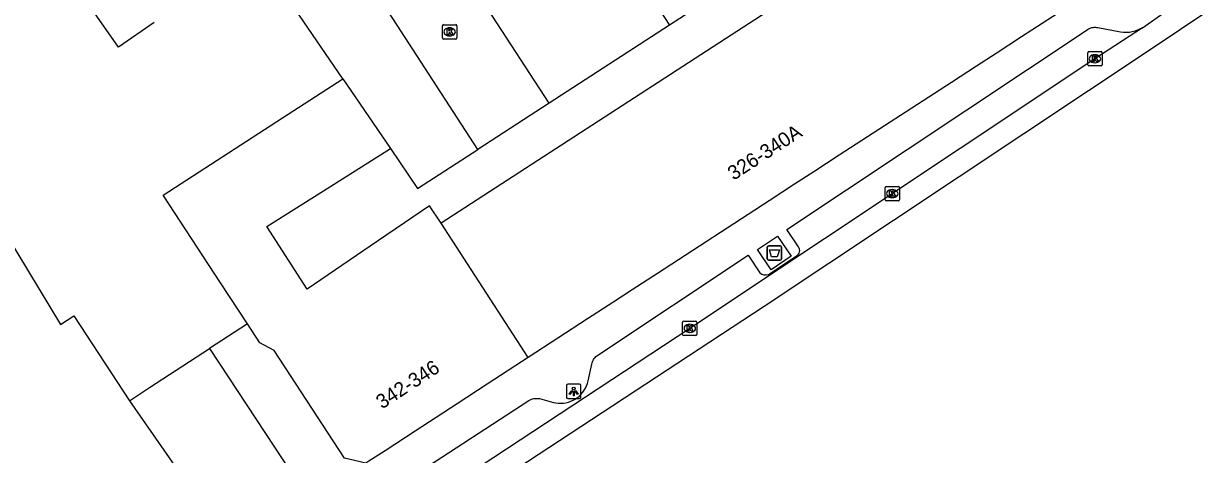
# Model space of a CAD drawing. Extents: x 159222 to 160346, y 381249 to 382166.
# Drawn here: x 160056.7 to 160138.9, y 381586.7 to 381616.7 of the extents above; entities that cross this region are included whole.
import ezdxf

# ---------------------------------------------------------------- set-up
doc = ezdxf.new("R2010")
doc.units = 0
for name, color, linetype in [('IMGEO_Afval_apart_plaats', 7, 'Continuous'), ('IMGEO_Kolk', 7, 'Continuous'), ('IMGEO_Lichtpunt', 7, 'Continuous'), ('IMGEO_Pand', 7, 'Continuous'), ('IMGEO_Pand_nummerreeks', 7, 'Continuous'), ('IMGEO_Pand_overbouw', 7, 'Continuous'), ('IMGEO_Parkeervlak_open', 7, 'Continuous'), ('IMGEO_Rijbaan_lokaal_gesloten', 7, 'Continuous'), ('IMGEO_Rijbaan_lokaal_open', 7, 'Continuous'), ('IMGEO_Voetpad_gesloten', 7, 'Continuous'), ('IMGEO_Voetpad_open', 7, 'Continuous')]:
    doc.layers.add(name, color=color, linetype=linetype)

msp = doc.modelspace()

# ---------------------------------------------------------------- linework, layer by layer
at = {"layer": 'IMGEO_Afval_apart_plaats'}
for p, q in [((160108.477, 381600.312), (160108.477, 381601.112)), ((160108.477, 381601.112), (160108.477, 381600.312)), ((160108.577, 381601.212), (160109.367, 381601.212)), ((160109.367, 381601.212), (160108.577, 381601.212)), ((160109.467, 381601.112), (160109.467, 381600.312)), ((160109.467, 381600.312), (160109.467, 381601.112)), ((160109.367, 381600.212), (160108.577, 381600.212)), ((160108.577, 381600.212), (160109.367, 381600.212))]:
    msp.add_line(p, q, dxfattribs=at)
msp.add_lwpolyline([(160108.62, 381600.926), (160109.324, 381600.926), (160109.175, 381600.456), (160108.769, 381600.456), (160108.62, 381600.926)], dxfattribs=at)
for centre, start, end in [((160108.577, 381601.112), 90, 180), ((160108.577, 381601.112), 90, 180), ((160109.367, 381601.112), 0, 90), ((160109.367, 381601.112), 360, 90), ((160108.577, 381600.312), 180, 270), ((160108.577, 381600.312), 180, 270), ((160109.367, 381600.312), 270, 0), ((160109.367, 381600.312), 270, 0)]:
    msp.add_arc(centre, 0.1, start, end, dxfattribs=at)
at = {"layer": 'IMGEO_Kolk'}
for p, q in [((160085.845, 381615.716), (160085.845, 381616.568)), ((160085.92, 381616.642), (160086.772, 381616.642)), ((160086.333, 381616.422), (160086.358, 381616.422)), ((160086.846, 381616.568), (160086.846, 381615.716)), ((160086.772, 381615.642), (160085.92, 381615.642)), ((160086.356, 381615.862), (160086.331, 381615.862)), ((160130.8, 381613.837), (160130.8, 381614.689)), ((160130.875, 381614.763), (160131.727, 381614.763)), ((160131.801, 381614.689), (160131.801, 381613.837)), ((160131.727, 381613.763), (160130.875, 381613.763)), ((160131.311, 381613.983), (160131.286, 381613.983)), ((160131.288, 381614.543), (160131.313, 381614.543)), ((160116.68, 381604.43), (160116.68, 381605.282)), ((160116.755, 381605.356), (160117.607, 381605.356)), ((160117.168, 381605.136), (160117.193, 381605.136)), ((160117.681, 381605.282), (160117.681, 381604.43)), ((160117.607, 381604.356), (160116.755, 381604.356)), ((160117.191, 381604.576), (160117.166, 381604.576)), ((160102.576, 381595.035), (160102.576, 381595.887)), ((160102.651, 381595.961), (160103.503, 381595.961)), ((160103.064, 381595.741), (160103.089, 381595.741)), ((160103.577, 381595.887), (160103.577, 381595.035)), ((160103.503, 381594.961), (160102.651, 381594.961)), ((160103.087, 381595.181), (160103.062, 381595.181))]:
    msp.add_line(p, q, dxfattribs=at)
for points in [[(160085.845, 381615.716), (160085.845, 381616.568)], [(160085.92, 381616.642), (160086.772, 381616.642)], [(160086.166, 381616.342), (160086.289, 381616.342), (160086.289, 381616.191), (160086.419, 381616.342), (160086.583, 381616.342), (160086.437, 381616.191), (160086.59, 381615.942), (160086.438, 381615.942), (160086.353, 381616.106), (160086.289, 381616.039), (160086.289, 381615.942), (160086.166, 381615.942), (160086.166, 381616.342)], [(160086.846, 381616.568), (160086.846, 381615.716)], [(160086.772, 381615.642), (160085.92, 381615.642)], [(160130.8, 381613.837), (160130.8, 381614.689)], [(160130.875, 381614.763), (160131.727, 381614.763)], [(160131.801, 381614.689), (160131.801, 381613.837)], [(160131.727, 381613.763), (160130.875, 381613.763)], [(160131.121, 381614.463), (160131.244, 381614.463), (160131.244, 381614.312), (160131.374, 381614.463), (160131.538, 381614.463), (160131.392, 381614.312), (160131.545, 381614.063), (160131.393, 381614.063), (160131.308, 381614.227), (160131.244, 381614.16), (160131.244, 381614.063), (160131.121, 381614.063), (160131.121, 381614.463)], [(160116.68, 381604.43), (160116.68, 381605.282)], [(160116.755, 381605.356), (160117.607, 381605.356)], [(160117.001, 381605.056), (160117.124, 381605.056), (160117.124, 381604.905), (160117.254, 381605.056), (160117.418, 381605.056), (160117.272, 381604.905), (160117.425, 381604.656), (160117.273, 381604.656), (160117.188, 381604.82), (160117.124, 381604.753), (160117.124, 381604.656), (160117.001, 381604.656), (160117.001, 381605.056)], [(160117.681, 381605.282), (160117.681, 381604.43)], [(160117.607, 381604.356), (160116.755, 381604.356)], [(160102.576, 381595.035), (160102.576, 381595.887)], [(160102.651, 381595.961), (160103.503, 381595.961)], [(160102.897, 381595.661), (160103.02, 381595.661), (160103.02, 381595.51), (160103.15, 381595.661), (160103.314, 381595.661), (160103.168, 381595.51), (160103.321, 381595.261), (160103.169, 381595.261), (160103.084, 381595.425), (160103.02, 381595.358), (160103.02, 381595.261), (160102.897, 381595.261), (160102.897, 381595.661)], [(160103.577, 381595.887), (160103.577, 381595.035)], [(160103.503, 381594.961), (160102.651, 381594.961)]]:
    msp.add_lwpolyline(points, dxfattribs=at)
for centre, start, end in [((160085.922, 381616.566), 91.55205, 178.44795), ((160085.922, 381616.566), 91.55205, 178.44795), ((160086.77, 381616.566), 1.55205, 88.44795), ((160086.77, 381616.566), 1.55205, 88.44795), ((160085.922, 381615.718), 181.55205, 268.44795), ((160085.922, 381615.718), 181.55205, 268.44795), ((160086.77, 381615.718), 271.55205, 358.44795), ((160086.77, 381615.718), 271.55205, 358.44795), ((160130.877, 381614.687), 91.55205, 178.44795), ((160130.877, 381614.687), 91.55205, 178.44795), ((160131.725, 381614.687), 1.55205, 88.44795), ((160131.725, 381614.687), 1.55205, 88.44795), ((160130.877, 381613.839), 181.55205, 268.44795), ((160130.877, 381613.839), 181.55205, 268.44795), ((160131.725, 381613.839), 271.55205, 358.44795), ((160131.725, 381613.839), 271.55205, 358.44795), ((160116.757, 381605.28), 91.55205, 178.44795), ((160116.757, 381605.28), 91.55205, 178.44795), ((160117.605, 381605.28), 1.55205, 88.44795), ((160117.605, 381605.28), 1.55205, 88.44795), ((160116.757, 381604.432), 181.55205, 268.44795), ((160116.757, 381604.432), 181.55205, 268.44795), ((160117.605, 381604.432), 271.55205, 358.44795), ((160117.605, 381604.432), 271.55205, 358.44795), ((160102.653, 381595.885), 91.55205, 178.44795), ((160102.653, 381595.885), 91.55205, 178.44795), ((160103.501, 381595.885), 1.55205, 88.44795), ((160103.501, 381595.885), 1.55205, 88.44795), ((160102.653, 381595.037), 181.55205, 268.44795), ((160102.653, 381595.037), 181.55205, 268.44795), ((160103.501, 381595.037), 271.55205, 358.44795), ((160103.501, 381595.037), 271.55205, 358.44795)]:
    msp.add_arc(centre, 0.0765, start, end, dxfattribs=at)
for centre, major_axis, ratio, start_param, end_param in [((160086.332, 381616.142), (-0.387, 0.002), 0.722429, 4.712389, 7.853982), ((160086.357, 381616.142), (-0.39, 0.002), 0.717154, 1.570796, 4.712389), ((160131.287, 381614.263), (-0.387, 0.002), 0.722429, 4.712389, 7.853982), ((160131.312, 381614.263), (-0.39, 0.002), 0.717154, 1.570796, 4.712389), ((160117.167, 381604.856), (-0.387, 0.002), 0.722429, 4.712389, 7.853982), ((160117.192, 381604.856), (-0.39, 0.002), 0.717154, 1.570796, 4.712389), ((160103.063, 381595.461), (-0.387, 0.002), 0.722429, 4.712389, 7.853982), ((160103.088, 381595.461), (-0.39, 0.002), 0.717154, 1.570796, 4.712389)]:
    msp.add_ellipse(centre, major_axis=major_axis, ratio=ratio, start_param=start_param, end_param=end_param, dxfattribs=at)
at = {"layer": 'IMGEO_Lichtpunt'}
for p, q in [((160095.391, 381591.565), (160094.583, 381591.565)), ((160095.391, 381591.565), (160094.583, 381591.565)), ((160094.489, 381591.47), (160094.489, 381590.663)), ((160094.489, 381591.47), (160094.489, 381590.663)), ((160095.485, 381590.663), (160095.485, 381591.47)), ((160095.485, 381590.663), (160095.485, 381591.47)), ((160094.583, 381590.569), (160095.391, 381590.569)), ((160094.583, 381590.569), (160095.391, 381590.569))]:
    msp.add_line(p, q, dxfattribs=at)
for points in [[(160094.863, 381591.134), (160094.902, 381591.106), (160094.714, 381590.844), (160094.676, 381590.871), (160094.863, 381591.134)], [(160094.965, 381591.086), (160095.012, 381591.086), (160095.012, 381590.764), (160094.965, 381590.764), (160094.965, 381591.086)], [(160095.075, 381591.106), (160095.113, 381591.133), (160095.3, 381590.871), (160095.261, 381590.843), (160095.075, 381591.106)]]:
    msp.add_lwpolyline(points, dxfattribs=at)
msp.add_circle((160094.988, 381591.268), 0.0994, dxfattribs=at)
for centre, start, end in [((160094.583, 381591.47), 90, 180), ((160094.583, 381591.47), 90, 180), ((160095.391, 381591.47), 0, 90), ((160095.391, 381591.47), 0, 90), ((160094.583, 381590.663), 180, 270), ((160094.583, 381590.663), 180, 270), ((160095.391, 381590.663), 270, 0), ((160095.391, 381590.663), 270, 360)]:
    msp.add_arc(centre, 0.0946, start, end, dxfattribs=at)
at = {"layer": 'IMGEO_Pand'}
for points in [[(160117.326, 381623.315), (160085.755, 381602.808)], [(160065.765, 381616.793), (160063.267, 381615.071), (160060.469, 381619.108), (160062.833, 381620.746)], [(160130.515, 381618.603), (160126.18, 381615.784), (160124.411, 381614.634), (160123.062, 381613.756), (160121.301, 381612.611), (160113.487, 381607.529), (160111.719, 381606.379), (160110.378, 381605.507), (160108.609, 381604.357), (160100.827, 381599.296), (160099.06, 381598.147), (160097.719, 381597.275), (160095.951, 381596.125), (160091.81, 381593.432)], [(160080.507, 381586.051), (160079.028, 381586.399), (160074.124, 381593.909), (160073.116, 381594.445), (160072.253, 381595.767), (160070.382, 381598.632), (160066.385, 381604.751), (160074.71, 381610.148), (160078.905, 381612.867)], [(160078.905, 381612.867), (160082.22, 381607.999)], [(160032.866, 381587.856), (160026.803, 381598.447), (160049.627, 381611.625), (160059.237, 381595.737), (160060.16, 381596.34), (160064.034, 381590.405)], [(160085.755, 381602.808), (160084.945, 381603.999), (160080.811, 381601.187), (160076.424, 381598.203), (160073.61, 381602.559), (160077.994, 381605.329), (160082.22, 381607.999)], [(160091.81, 381593.432), (160085.755, 381602.808)], [(160064.034, 381590.405), (160065.441, 381591.324), (160069.627, 381594.058), (160076.071, 381584.244), (160076.584, 381584.042), (160076.802, 381583.707)], [(160091.81, 381593.432), (160088.964, 381591.573), (160086.871, 381590.207), (160083.94, 381588.293), (160081.847, 381586.926), (160080.717, 381586.188), (160080.507, 381586.051)], [(160064.034, 381590.405), (160071.216, 381580.08)]]:
    msp.add_lwpolyline(points, dxfattribs=at)
at = {"layer": 'IMGEO_Pand_overbouw'}
msp.add_lwpolyline([(160069.627, 381594.058), (160076.071, 381584.244), (160076.584, 381584.042), (160076.802, 381583.707), (160078.623, 381584.859), (160080.507, 381586.051), (160079.028, 381586.399), (160074.124, 381593.909), (160073.116, 381594.445), (160072.253, 381595.767)], close=True, dxfattribs=at)
at = {"layer": 'IMGEO_Parkeervlak_open'}
for points in [[(160078.905, 381612.867), (160072.874, 381621.721)], [(160101.666, 381616.599), (160093.287, 381611.166)], [(160082.22, 381607.999), (160084.116, 381605.216), (160088.317, 381607.943)]]:
    msp.add_lwpolyline(points, dxfattribs=at)
at = {"layer": 'IMGEO_Rijbaan_lokaal_gesloten'}
for points in [[(160138.741, 381619.241), (160139.591, 381617.866), (160137.265, 381616.308), (160135.358, 381615.03), (160108.254, 381596.98), (160074.47, 381574.782), (160035.773, 381549.819), (160006.52, 381531.153), (160002.266, 381528.592)], [(160134.606, 381616.433), (160136.26, 381617.573), (160137.64, 381618.525)], [(160134.606, 381616.433), (160131.298, 381614.262), (160103.074, 381595.46), (160087.579, 381585.252), (160070.937, 381574.339)]]:
    msp.add_lwpolyline(points, dxfattribs=at)
at = {"layer": 'IMGEO_Rijbaan_lokaal_open'}
for points in [[(160093.287, 381611.166), (160080.393, 381631.009), (160088.785, 381636.465), (160101.666, 381616.599)], [(160088.317, 381607.943), (160072.777, 381631.935)], [(160117.326, 381623.315), (160116.481, 381624.633), (160114.624, 381625), (160101.666, 381616.599)], [(160093.287, 381611.166), (160088.317, 381607.943)]]:
    msp.add_lwpolyline(points, dxfattribs=at)
at = {"layer": 'IMGEO_Voetpad_gesloten'}
msp.add_lwpolyline([(160109.186, 381601.898), (160110.134, 381600.487), (160108.741, 381599.551), (160107.793, 381600.962), (160109.186, 381601.898)], dxfattribs=at)
at = {"layer": 'IMGEO_Voetpad_open'}
for points in [[(160110.656, 381601.137), (160109.83, 381602.351), (160130.759, 381616.281), (160130.792, 381616.305), (160130.862, 381616.347), (160130.934, 381616.383), (160131.01, 381616.413), (160131.088, 381616.435), (160131.168, 381616.451), (160131.249, 381616.459), (160131.331, 381616.461), (160131.412, 381616.454), (160131.492, 381616.441), (160133.091, 381616.134), (160133.295, 381616.113), (160133.5, 381616.11), (160133.704, 381616.125), (160133.906, 381616.159), (160134.105, 381616.21), (160134.298, 381616.279), (160134.484, 381616.365), (160134.606, 381616.433)], [(160082.741, 381584.465), (160091.857, 381590.422), (160091.869, 381590.429), (160091.952, 381590.473), (160092.039, 381590.51), (160092.129, 381590.539), (160092.221, 381590.559), (160092.314, 381590.572), (160092.409, 381590.575), (160092.503, 381590.571), (160092.596, 381590.558), (160093.573, 381590.298), (160093.746, 381590.262), (160093.921, 381590.241), (160094.097, 381590.236), (160094.273, 381590.247), (160094.448, 381590.273), (160094.619, 381590.315), (160094.786, 381590.372), (160094.948, 381590.444), (160095.102, 381590.53), (160095.248, 381590.629), (160095.384, 381590.741), (160095.51, 381590.864), (160095.624, 381590.999), (160095.726, 381591.143), (160095.815, 381591.295), (160095.889, 381591.455), (160095.949, 381591.621), (160095.994, 381591.792), (160095.998, 381591.809), (160096.253, 381592.971), (160096.272, 381593.05), (160096.299, 381593.132), (160096.334, 381593.211), (160096.376, 381593.287), (160096.424, 381593.359), (160096.479, 381593.426), (160096.539, 381593.488), (160096.605, 381593.545), (160096.675, 381593.595), (160107.143, 381600.562), (160107.947, 381599.327)], [(160108.562, 381599.219), (160110.517, 381600.522)]]:
    msp.add_lwpolyline(points, dxfattribs=at)
for centre, radius, start, end in [((160110.326, 381600.888), 0.413, 297.51748, 37.01094), ((160108.347, 381599.801), 0.621, 229.83387, 290.24585)]:
    msp.add_arc(centre, radius, start, end, dxfattribs=at)

# ---------------------------------------------------------------- texts
at = {"layer": 'IMGEO_Pand_nummerreeks'}
for s, rotation, p in [('326-340A', 33.03713, (160106.13, 381605.751)), ('342-346', 33.14552, (160081.635, 381589.797))]:
    msp.add_text(s, height=1, rotation=rotation, dxfattribs=at).set_placement(p)

doc.saveas('drawing.dxf')
